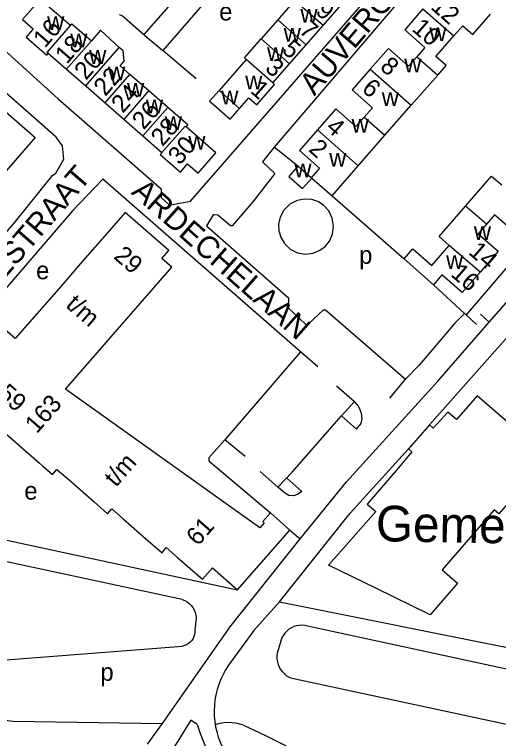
# Model space of a CAD drawing. Extents: x 157768 to 159790, y 387230 to 389604.
# Drawn here: x 158763.5 to 158872.2, y 388688.8 to 388851.2 of the extents above; entities that cross this region are included whole.
import ezdxf

# ---------------------------------------------------------------- set-up
doc = ezdxf.new("R2010")
doc.units = 0
for name, color, linetype in [('BLT_Basislijn', 7, 'Continuous'), ('BLT_Bebouwing', 7, 'Continuous'), ('BLT_Bebouwing_beschrifting', 7, 'Continuous'), ('BLT_Centroide', 7, 'Continuous'), ('BLT_Huisnummer', 7, 'Continuous'), ('BLT_Huisnummer_ tussenligend', 7, 'Continuous'), ('BLT_Huisnummer_reeks', 7, 'Continuous'), ('BLT_Onderverdeling_panden', 7, 'Continuous'), ('BLT_Straatnaam', 7, 'Continuous')]:
    doc.layers.add(name, color=color, linetype=linetype)

msp = doc.modelspace()

# ---------------------------------------------------------------- linework, layer by layer
at = {"layer": 'BLT_Basislijn'}
for p, q in [((158870.13, 388782.18), (158932.57, 388853.72)), ((158919.14, 388847.41), (158864.96, 388783.82)), ((158772.86, 388823.69), (158755.86, 388838.68)), ((158774.29, 388821.78), (158772.86, 388823.69)), ((158774.56, 388818.76), (158774.29, 388821.78)), ((158827.17, 388817.21), (158821.82, 388821.45)), ((158772.76, 388815.64), (158774.56, 388818.76)), ((158772.08, 388815.12), (158772.76, 388815.64)), ((158763.71, 388804.79), (158772.08, 388815.12)), ((158834.86, 388810.52), (158851.01, 388796.39)), ((158743.52, 388781.54), (158763.71, 388804.79)), ((158856.71, 388759.16), (158890.42, 388797.2)), ((158864.6, 388784.16), (158857.63, 388790.61)), ((158864.96, 388783.82), (158864.6, 388784.16)), ((158867.27, 388781.69), (158864.96, 388783.82)), ((158870.13, 388782.18), (158868.17, 388784)), ((158827.73, 388775.55), (158810.75, 388755.8)), ((158831.68, 388772.19), (158827.73, 388775.55)), ((158847.82, 388765.15), (158851.33, 388769.39)), ((158835.84, 388767.95), (158839.89, 388764.39)), ((158836.98, 388761.19), (158839.89, 388764.39)), ((158818.67, 388748.73), (158822.63, 388745.15)), ((158720.25, 388742.24), (158813.63, 388722.13)), ((158801.2, 388719.95), (158725.19, 388736.3)), ((158825.38, 388735.5), (158827.68, 388733.57)), ((158811.61, 388713.38), (158827.68, 388733.57)), ((158823.04, 388719.47), (158906.54, 388702.76)), ((158804.34, 388715.7), (158804.04, 388713.14)), ((158804.04, 388713.14), (158803.99, 388712.65)), ((158811.61, 388713.38), (158810.49, 388711.8)), ((158928.44, 388692.59), (158829.32, 388714.01)), ((158810.49, 388711.8), (158796.8, 388692.4)), ((158823.5, 388711.17), (158822.51, 388707.91)), ((158739.81, 388704.77), (158801.24, 388709.52)), ((158825.48, 388702.38), (158925.89, 388680.82)), ((158796.65, 388692.18), (158793.34, 388687.49)), ((158796.8, 388692.4), (158796.65, 388692.18)), ((158814.98, 388691.75), (158819.78, 388689.5)), ((158819.78, 388689.5), (158841.9, 388678.5))]:
    msp.add_line(p, q, dxfattribs=at)
for points in [[(158930.23, 388859.87), (158887.65, 388896.77), (158887.02, 388896.73), (158885.14, 388895), (158879.68, 388888.63), (158875.82, 388884.11), (158850.5, 388855.06), (158821.82, 388821.45)], [(158789.53, 388886.89), (158788.49, 388885.64), (158785.21, 388881.92), (158784.98, 388879.44), (158784.49, 388878.47), (158764.24, 388855.08), (158762.68, 388853.33), (158759.96, 388853.37), (158758.72, 388851.81), (158758.75, 388845.47), (158773.35, 388832.32), (158796.48, 388812.13), (158796.48, 388810.15), (158798.16, 388808.6), (158798.65, 388808.52), (158803.01, 388809.33), (158845.58, 388858.2), (158846.64, 388859.35)], [(158800.84, 388876.69), (158811.05, 388867.82), (158792.59, 388846.72)], [(158835.32, 388869.21), (158826.46, 388876.73), (158825.83, 388876.57), (158796.83, 388843.16)], [(158786.99, 388851.21), (158787.77, 388850.97), (158792.59, 388846.72)], [(158792.59, 388846.72), (158792.81, 388846.53), (158796.83, 388843.16)], [(158804.33, 388836.83), (158797.89, 388842.28), (158796.83, 388843.16)], [(158821.82, 388821.45), (158819.25, 388818.17), (158822.02, 388815.54), (158817.04, 388809.17), (158812.4, 388803.85), (158812.02, 388803.85), (158809.22, 388806.18), (158808.43, 388806.29), (158808.17, 388806.29), (158806.67, 388803.85), (158825.05, 388787.68), (158825.08, 388785.38), (158828.88, 388781.77), (158829.46, 388781.75), (158832.94, 388785), (158833.36, 388785), (158851.33, 388769.39)], [(158827.73, 388775.55), (158783.36, 388814.3), (158776.54, 388807.15), (158756.87, 388784.38)], [(158822.9, 388802.68), (158823.31, 388801.26), (158824.15, 388799.84), (158825.45, 388798.62), (158827.1, 388797.79), (158828.91, 388797.49), (158830.63, 388797.71), (158832.11, 388798.33), (158833.26, 388799.19), (158834.24, 388800.39), (158834.93, 388801.94), (158835.18, 388803.73), (158834.89, 388805.56), (158834.09, 388807.18), (158832.94, 388808.43), (158831.64, 388809.26), (158830.27, 388809.72), (158828.68, 388809.84), (158826.97, 388809.5), (158825.34, 388808.65), (158824.04, 388807.35), (158823.19, 388805.78), (158822.84, 388804.17), (158822.9, 388802.68)], [(158864.6, 388784.16), (158862.43, 388782), (158854.4, 388772.55), (158851.33, 388769.39)], [(158827.68, 388733.57), (158838.08, 388746.34), (158858.62, 388768.99), (158870.13, 388782.18)], [(158836.98, 388761.19), (158840.35, 388758.19), (158841.36, 388759.47), (158841.61, 388760.62), (158841.49, 388761.72), (158841.19, 388762.53), (158840.77, 388763.33), (158839.89, 388764.39)], [(158822.63, 388745.15), (158825.91, 388748.55), (158836.98, 388761.19)], [(158810.75, 388755.8), (158807.15, 388751.79), (158807.2, 388751.08), (158820.98, 388739.39)], [(158815.33, 388752.04), (158810.75, 388755.8)], [(158823.04, 388719.47), (158838.9, 388739.31), (158852.02, 388753.77)], [(158824.65, 388747.21), (158828.02, 388744.19), (158827.06, 388743.56), (158826.17, 388743.26), (158825.15, 388743.34), (158824.17, 388743.9), (158822.63, 388745.15)], [(158801.2, 388719.95), (158801.76, 388719.72), (158802.29, 388719.42), (158802.77, 388719.05), (158803.2, 388718.63), (158803.57, 388718.15), (158803.87, 388717.63), (158804.1, 388717.07), (158804.26, 388716.48), (158804.33, 388715.88), (158804.34, 388715.7)], [(158823.04, 388719.47), (158817.26, 388713.02), (158811.59, 388705.22)], [(158694.06, 388715.21), (158699.84, 388706.92), (158702.25, 388704.75), (158708.09, 388701.57), (158713.74, 388699.41), (158718.27, 388698.35), (158743.7, 388695.24), (158763.17, 388692.7), (158796.65, 388692.18)], [(158829.32, 388714.01), (158828.71, 388714.15), (158828.09, 388714.2), (158827.47, 388714.17), (158826.86, 388714.07), (158826.26, 388713.88), (158825.7, 388713.63), (158825.17, 388713.3), (158824.69, 388712.9), (158824.26, 388712.45), (158823.9, 388711.95), (158823.6, 388711.4), (158823.5, 388711.17)], [(158803.99, 388712.65), (158803.94, 388712.15), (158803.81, 388711.66), (158803.61, 388711.19), (158803.34, 388710.77), (158803, 388710.39), (158802.61, 388710.07), (158802.18, 388709.81), (158801.71, 388709.63), (158801.24, 388709.52)], [(158822.51, 388707.91), (158822.44, 388707.27), (158822.46, 388706.63), (158822.56, 388705.99), (158822.73, 388705.38), (158822.98, 388704.79), (158823.3, 388704.23), (158823.69, 388703.72), (158824.14, 388703.26), (158824.64, 388702.86), (158825.19, 388702.52), (158825.48, 388702.38)], [(158811.59, 388705.22), (158810.94, 388704.2), (158810.35, 388703.15), (158809.84, 388702.06), (158809.4, 388700.93), (158809.03, 388699.79), (158808.74, 388698.61), (158808.53, 388697.43), (158808.4, 388696.23), (158808.35, 388695.02), (158808.38, 388693.81), (158808.48, 388692.61), (158808.6, 388691.89)], [(158804.52, 388691.91), (158803.15, 388692.93), (158795.79, 388681.11)], [(158814.98, 388691.75), (158814.12, 388692.01), (158813.24, 388692.2), (158812.35, 388692.31), (158811.45, 388692.34), (158810.55, 388692.29), (158809.66, 388692.16), (158808.79, 388691.95), (158808.6, 388691.89)], [(158804.52, 388691.91), (158805.04, 388690.34), (158805.63, 388688.8), (158806.3, 388687.3), (158807.04, 388685.83), (158807.85, 388684.39), (158808.73, 388682.99), (158809.68, 388681.64), (158810.69, 388680.34), (158811.76, 388679.09), (158812.65, 388678.13)], [(158808.6, 388691.89), (158808.67, 388691.42), (158808.94, 388690.24), (158809.28, 388689.09), (158809.7, 388687.96), (158810.08, 388687.12)]]:
    msp.add_lwpolyline(points, dxfattribs=at)
at = {"layer": 'BLT_Bebouwing'}
for p, q in [((158826.41, 388854.37), (158822.65, 388850.08)), ((158832.82, 388848.77), (158836.57, 388853.06)), ((158822.65, 388850.08), (158818.9, 388845.78)), ((158829.06, 388844.47), (158832.82, 388848.77)), ((158825.31, 388840.18), (158829.06, 388844.47)), ((158771.1, 388842.53), (158775.21, 388838.94)), ((158815.53, 388841.15), (158809.45, 388834.18)), ((158821.55, 388835.89), (158825.31, 388840.18)), ((158775.21, 388838.94), (158779.5, 388835.2)), ((158793.69, 388834.11), (158789.44, 388837.81)), ((158852.64, 388830.92), (158858.57, 388837.65)), ((158779.5, 388835.2), (158783.86, 388831.41)), ((158797.95, 388830.4), (158793.69, 388834.11)), ((158783.86, 388831.41), (158788.11, 388827.7)), ((158788.11, 388827.7), (158792.36, 388823.99)), ((158792.36, 388823.99), (158796.62, 388820.29)), ((158840.73, 388817.31), (158846.71, 388824.14)), ((158830.17, 388814.62), (158827.17, 388817.21)), ((158834.86, 388810.52), (158840.73, 388817.31)), ((158830.27, 388814.52), (158834.86, 388810.52)), ((158783.3, 388800.99), (158778.37, 388795.35)), ((158857.63, 388790.61), (158851.01, 388796.39)), ((158778.37, 388795.35), (158773.43, 388789.7)), ((158773.43, 388789.7), (158768.49, 388784.05)), ((158763.65, 388778.52), (158756.87, 388784.38)), ((158768.49, 388784.05), (158763.65, 388778.52)), ((158856.71, 388759.16), (158852.02, 388753.77)), ((158763.55, 388755.44), (158769.16, 388750.54)), ((158775.77, 388746.79), (158781.37, 388741.87)), ((158825.38, 388735.5), (158820.98, 388739.39)), ((158787.93, 388738.06), (158793.55, 388733.17))]:
    msp.add_line(p, q, dxfattribs=at)
for points in [[(158776.06, 388848.79), (158769.3, 388854.68), (158765.33, 388850.12), (158767.72, 388848.03), (158766.11, 388846.19), (158770.76, 388842.14), (158771.1, 388842.53)], [(158855.27, 388852.5), (158851.17, 388847.81), (158855.71, 388843.85), (158853.88, 388841.75)], [(158862.2, 388846.44), (158864.19, 388848.72), (158866.45, 388846.74), (158870.42, 388851.29)], [(158776.06, 388848.79), (158776.4, 388849.18), (158780.79, 388845.35)], [(158787.02, 388843.86), (158782.84, 388847.69), (158780.79, 388845.35)], [(158858.57, 388837.65), (158860.47, 388839.83), (158858.17, 388841.83), (158862.2, 388846.44)], [(158815.53, 388841.15), (158815.15, 388841.49), (158818.9, 388845.78)], [(158789.44, 388837.81), (158787.28, 388839.74), (158788.15, 388840.74), (158787.9, 388843.09), (158787.02, 388843.86)], [(158853.88, 388841.75), (158852.05, 388839.66), (158847.51, 388843.62), (158843.44, 388838.97)], [(158843.44, 388838.97), (158839.37, 388834.31), (158843.92, 388830.33), (158842.06, 388828.21)], [(158814.05, 388830.16), (158816.15, 388832.57), (158817.96, 388831), (158821.94, 388835.55), (158821.55, 388835.89)], [(158746.44, 388798.69), (158768.14, 388823.54), (158755.52, 388834.58)], [(158809.45, 388834.18), (158807.34, 388831.78), (158808.18, 388831.04), (158811.94, 388827.75), (158814.05, 388830.16)], [(158802.07, 388826.05), (158802.44, 388826.48), (158797.95, 388830.4)], [(158846.71, 388824.14), (158852.64, 388830.92)], [(158842.06, 388828.21), (158840.21, 388826.09), (158835.68, 388830.04), (158831.6, 388825.37)], [(158796.62, 388820.29), (158796.25, 388819.86), (158800.79, 388815.9), (158802.36, 388817.7), (158804.74, 388815.63), (158808.75, 388820.23), (158802.07, 388826.05)], [(158831.6, 388825.37), (158827.52, 388820.7), (158832.03, 388816.75), (158830.17, 388814.62)], [(158827.17, 388817.21), (158825.12, 388814.87), (158828.21, 388812.17), (158830.27, 388814.52)], [(158864.83, 388808.23), (158866.76, 388810.44), (158870.7, 388814.96), (158872.99, 388813.05)], [(158861.17, 388799.44), (158858.9, 388801.43), (158864.83, 388808.23)], [(158774.95, 388767.2), (158798.84, 388794.51), (158796.58, 388796.51), (158798.17, 388798.26), (158788.4, 388806.82), (158783.3, 388800.99)], [(158879.96, 388806.97), (158875.9, 388802.31), (158871.35, 388806.28), (158869.51, 388804.16)], [(158869.51, 388804.16), (158867.66, 388802.04), (158872.18, 388798.1), (158868.08, 388793.4)], [(158851.01, 388796.39), (158852.97, 388798.64), (158857.23, 388794.93), (158861.17, 388799.44)], [(158868.08, 388793.4), (158864.1, 388788.83), (158859.54, 388792.8), (158857.63, 388790.61)], [(158820.98, 388739.39), (158819.29, 388737.46), (158819.59, 388737.2), (158818.59, 388736.05), (158774.95, 388767.2)], [(158876.34, 388757.98), (158867.45, 388765.71), (158862.79, 388760.35), (158860.87, 388762.01), (158857.58, 388758.4), (158856.71, 388759.16)], [(158752.46, 388755.06), (158757.45, 388760.77), (158763.55, 388755.44)], [(158852.02, 388753.77), (158852.8, 388753.09), (158850.14, 388750), (158842.73, 388741.4), (158844.65, 388739.69), (158834.08, 388727.68)], [(158769.16, 388750.54), (158769.78, 388750), (158772.07, 388748), (158773.05, 388749.18), (158775.77, 388746.79)], [(158877.18, 388744.79), (158872.28, 388739.16), (158871.24, 388740.07), (158859.56, 388726.65)], [(158781.37, 388741.87), (158784.39, 388739.22), (158785.34, 388740.3), (158787.93, 388738.06)], [(158813.63, 388722.13), (158825.38, 388735.5)], [(158793.55, 388733.17), (158796.67, 388730.47), (158797.61, 388731.62), (158800.15, 388729.4)], [(158800.15, 388729.4), (158805.76, 388724.51), (158807.99, 388727.05)], [(158807.99, 388727.05), (158813.63, 388722.13)], [(158859.56, 388726.65), (158863.04, 388723.62), (158856.86, 388716.52), (158844.71, 388722.49), (158834.08, 388727.68)]]:
    msp.add_lwpolyline(points, dxfattribs=at)
at = {"layer": 'BLT_Onderverdeling_panden'}
for p, q in [((158832.82, 388848.77), (158826.41, 388854.37)), ((158855.27, 388852.5), (158862.2, 388846.44)), ((158829.06, 388844.47), (158822.65, 388850.08)), ((158775.21, 388838.94), (158780.79, 388845.35)), ((158825.31, 388840.18), (158818.9, 388845.78)), ((158779.5, 388835.2), (158787.02, 388843.86)), ((158853.88, 388841.75), (158858.57, 388837.65)), ((158821.55, 388835.89), (158815.53, 388841.15)), ((158843.44, 388838.97), (158852.64, 388830.92)), ((158783.86, 388831.41), (158789.44, 388837.81)), ((158788.11, 388827.7), (158793.69, 388834.11)), ((158809.45, 388834.18), (158814.05, 388830.16)), ((158792.36, 388823.99), (158797.95, 388830.4)), ((158842.06, 388828.21), (158846.71, 388824.14)), ((158831.6, 388825.37), (158840.73, 388817.31)), ((158830.17, 388814.62), (158830.27, 388814.52)), ((158869.51, 388804.16), (158864.83, 388808.23)), ((158868.08, 388793.4), (158861.17, 388799.44))]:
    msp.add_line(p, q, dxfattribs=at)
for points in [[(158771.1, 388842.53), (158770.86, 388842.73), (158776.06, 388848.79)], [(158796.62, 388820.29), (158801.88, 388826.22), (158802.07, 388826.05)]]:
    msp.add_lwpolyline(points, dxfattribs=at)

# ---------------------------------------------------------------- texts
at = {"layer": 'BLT_Bebouwing_beschrifting'}
msp.add_text('Gemeenschapshuis', height=8, rotation=359, dxfattribs=at).set_placement((158844.65, 388733.07))
at = {"layer": 'BLT_Centroide'}
for s, p in [('e', (158809.49, 388849.91)), ('w', (158827.73, 388849.41)), ('w', (158770.83, 388847.78)), ('w', (158823.98, 388845.12)), ('w', (158856.69, 388845.27)), ('w', (158776.02, 388843.88)), ('w', (158780.27, 388840.17)), ('w', (158820.23, 388840.84)), ('w', (158851.06, 388838.25)), ('w', (158784.52, 388836.45)), ('w', (158815.32, 388834.44)), ('w', (158788.78, 388832.77)), ('w', (158809.94, 388831.05)), ('w', (158846, 388830.73)), ('w', (158793.03, 388829.05)), ('w', (158797.28, 388825.34)), ('w', (158839.24, 388824.69)), ('w', (158802.55, 388820.94)), ('w', (158834.19, 388817.11)), ('w', (158826.37, 388814.69)), ('w', (158866.7, 388800.66)), ('p', (158840.93, 388795.29)), ('w', (158860.45, 388794.16)), ('e', (158768.36, 388791.83)), ('e', (158765.71, 388742.38)), ('p', (158782.81, 388701.71))]:
    msp.add_text(s, height=4, dxfattribs=at).set_placement(p)
at = {"layer": 'BLT_Huisnummer'}
for s, rotation, p in [('9', 318.8305, (158830.91, 388851.62)), ('16', 48.9309, (158770.34, 388843.55)), ('10', 318.8409, (158852.57, 388847.77)), ('5', 318.8303, (158823.36, 388842.99)), ('20', 48.9276, (158779.57, 388836.34)), ('6', 318.8409, (158841.3, 388834.25)), ('24', 48.9283, (158787.86, 388828.93)), ('1', 318.8356, (158816.28, 388833.89)), ('30', 48.9315, (158800.62, 388817.26)), ('2', 318.8409, (158829.38, 388820.71)), ('16', 318.9164, (158861.29, 388792.75))]:
    msp.add_text(s, height=4, rotation=rotation, dxfattribs=at).set_placement(p)
at = {"layer": 'BLT_Huisnummer_ tussenligend'}
for s, rotation, p in [('12', 318.8409, (158856.79, 388852.68)), ('7', 318.8303, (158827.22, 388847.34)), ('18', 48.9309, (158775.26, 388839.93)), ('8', 318.8409, (158845.4, 388839.16)), ('3', 318.8356, (158819.57, 388838.86)), ('22', 48.9276, (158783.91, 388832.72)), ('26', 48.9283, (158792.54, 388825.18)), ('28', 48.9283, (158796.76, 388821.44)), ('4', 318.8409, (158833.24, 388825.52)), ('14', 318.9164, (158865.28, 388797.67))]:
    msp.add_text(s, height=4, rotation=rotation, dxfattribs=at).set_placement(p)
at = {"layer": 'BLT_Huisnummer_reeks'}
for s, rotation, p in [('29', 318.8767, (158785.58, 388796.68)), ('t/m', 318.8691, (158774.8, 388785.78)), ('59', 318.8748, (158759.48, 388765.73)), ('163', 48.7959, (158768.5, 388757.01)), ('t/m', 48.7959, (158786.29, 388745.01)), ('61', 48.7959, (158804.71, 388731.8))]:
    msp.add_text(s, height=4, rotation=rotation, dxfattribs=at).set_placement(p)
at = {"layer": 'BLT_Straatnaam'}
for s, rotation, p in [('AUVERGNELAAN', 49.4705, (158830.88, 388832.84)), ('MARNESTRAAT', 49.174, (158747.9, 388776.34)), ('ARDECHELAAN', 318.5663, (158789.53, 388811.11))]:
    msp.add_text(s, height=5, rotation=rotation, dxfattribs=at).set_placement(p)

doc.saveas('drawing.dxf')
